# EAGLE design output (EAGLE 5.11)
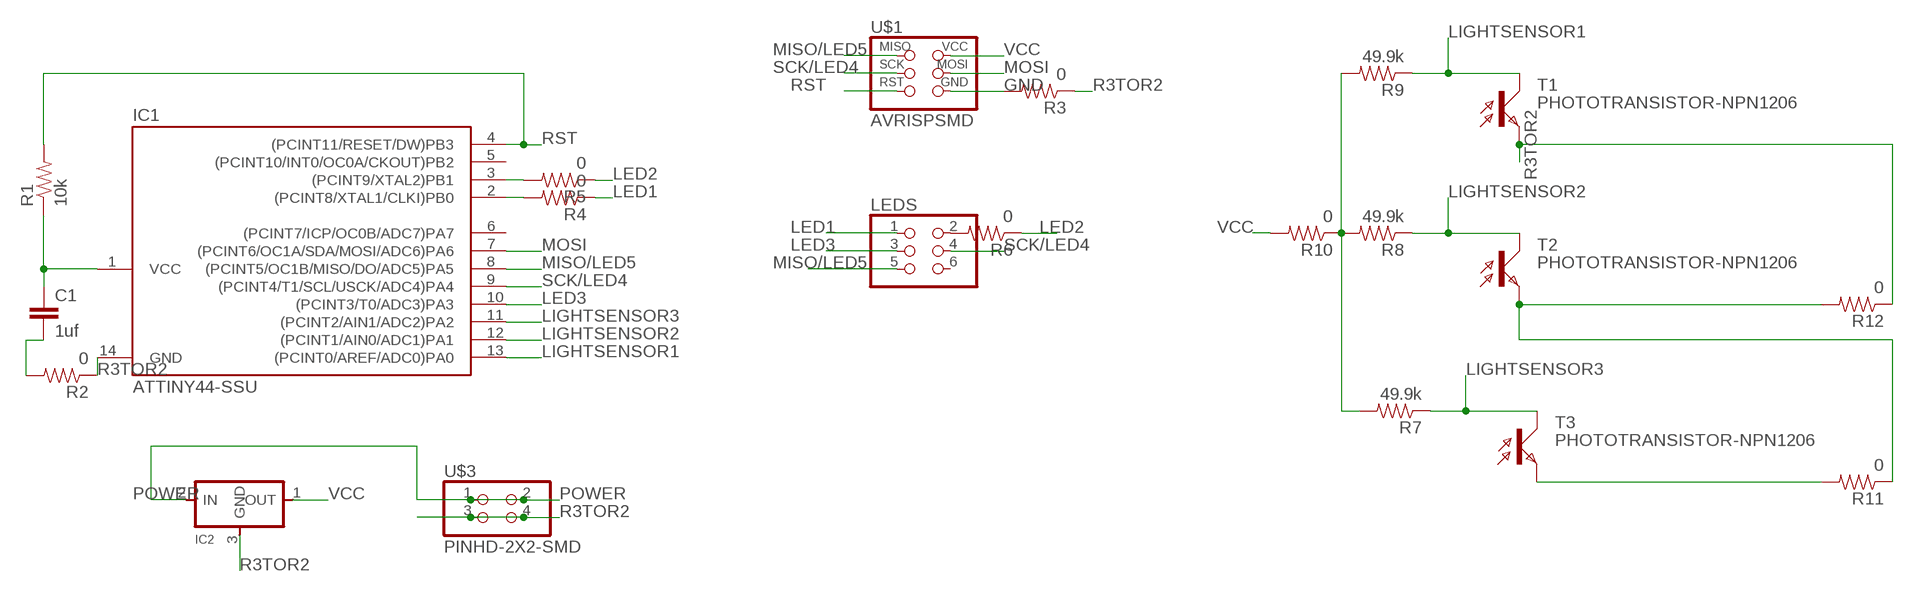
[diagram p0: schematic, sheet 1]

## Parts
C1  1uf  CAP1206  [1206]
IC1  ATTINY44-SSU  [SOIC14]
IC2  REGULATORSOT23  [SOT23]
LEDS  PINHD-2X3-SMD  [2X03SMD]
R1  10k  RESISTOR1206  [1206]
R2  0  RESISTOR1206  [1206]
R3  0  RESISTOR1206  [1206]
R4  0  RESISTOR1206  [1206]
R5  0  RESISTOR1206  [1206]
R6  0  RESISTOR1206  [1206]
R7  49.9k  RESISTOR1206  [1206]
R8  49.9k  RESISTOR1206  [1206]
R9  49.9k  RESISTOR1206  [1206]
R10  0  RESISTOR1206  [1206]
R11  0  RESISTOR1206  [1206]
R12  0  RESISTOR1206  [1206]
T1  PHOTOTRANSISTOR-NPN1206  [OP1206]
T2  PHOTOTRANSISTOR-NPN1206  [OP1206]
T3  PHOTOTRANSISTOR-NPN1206  [OP1206]
U$1  AVRISPSMD  [2X03SMD]
U$3  PINHD-2X2-SMD  [2X02SMD]

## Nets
GND: R3.2 U$1.6(GND)
LED1: LEDS.1 R4.1
LED2: R5.1 R6.1
LED3: IC1.10((PCINT3/T0/ADC3)PA3) LEDS.3
LIGHTSENSOR1: IC1.13((PCINT0/AREF/ADC0)PA0) R9.1 T1.COLLECTOR(C)
LIGHTSENSOR2: IC1.12((PCINT1/AIN0/ADC1)PA1) R8.1 T2.COLLECTOR(C)
LIGHTSENSOR3: IC1.11((PCINT2/AIN1/ADC2)PA2) R7.1 T3.COLLECTOR(C)
MISO/LED5: IC1.8((PCINT5/OC1B/MISO/DO/ADC5)PA5) LEDS.5 U$1.1(MISO)
MOSI: IC1.7((PCINT6/OC1A/SDA/MOSI/ADC6)PA6) U$1.4(MOSI)
N$1: IC1.3((PCINT9/XTAL2)PB1) R5.2
N$2: C1.2 R2.2
N$3: IC1.2((PCINT8/XTAL1/CLKI)PB0) R4.2
N$4: LEDS.2 R6.2
N$5: R7.2 R8.2 R9.2 R10.1
N$6: R11.2 T3.EMITTER(E)
N$7: R11.1 R12.2 T2.EMITTER(E)
POWER: IC2.2(IN) U$3.1 U$3.2
R3TOR2: IC1.14(GND) IC2.3(GND) R2.1 R3.1 R12.1 T1.EMITTER(E) U$3.3 U$3.4
RST: IC1.4((PCINT11/RESET/DW)PB3) R1.2 U$1.5(RST)
SCK/LED4: IC1.9((PCINT4/T1/SCL/USCK/ADC4)PA4) LEDS.4 U$1.3(SCK)
VCC: C1.1 IC1.1(VCC) IC2.1(OUT) R1.1 R10.2 U$1.2(VCC)
Unconnected: IC1.5((PCINT10/INT0/OC0A/CKOUT)PB2) IC1.6((PCINT7/ICP/OC0B/ADC7)PA7) LEDS.6

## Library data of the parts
C1 = SparkFun:CAP: Capacitor
IC1 = fab:ATTINY44
IC2 = ng:REGULATOR
LEDS = fab:PINHD-2X3-SMD: PIN HEADER
R1-R12 = SparkFun:RESISTOR: Resistor
T1-T3 = fab:PHOTOTRANSISTOR-NPN
U$1 = fab:AVRISP
U$3 = fab:PINHD-2X2-SMD

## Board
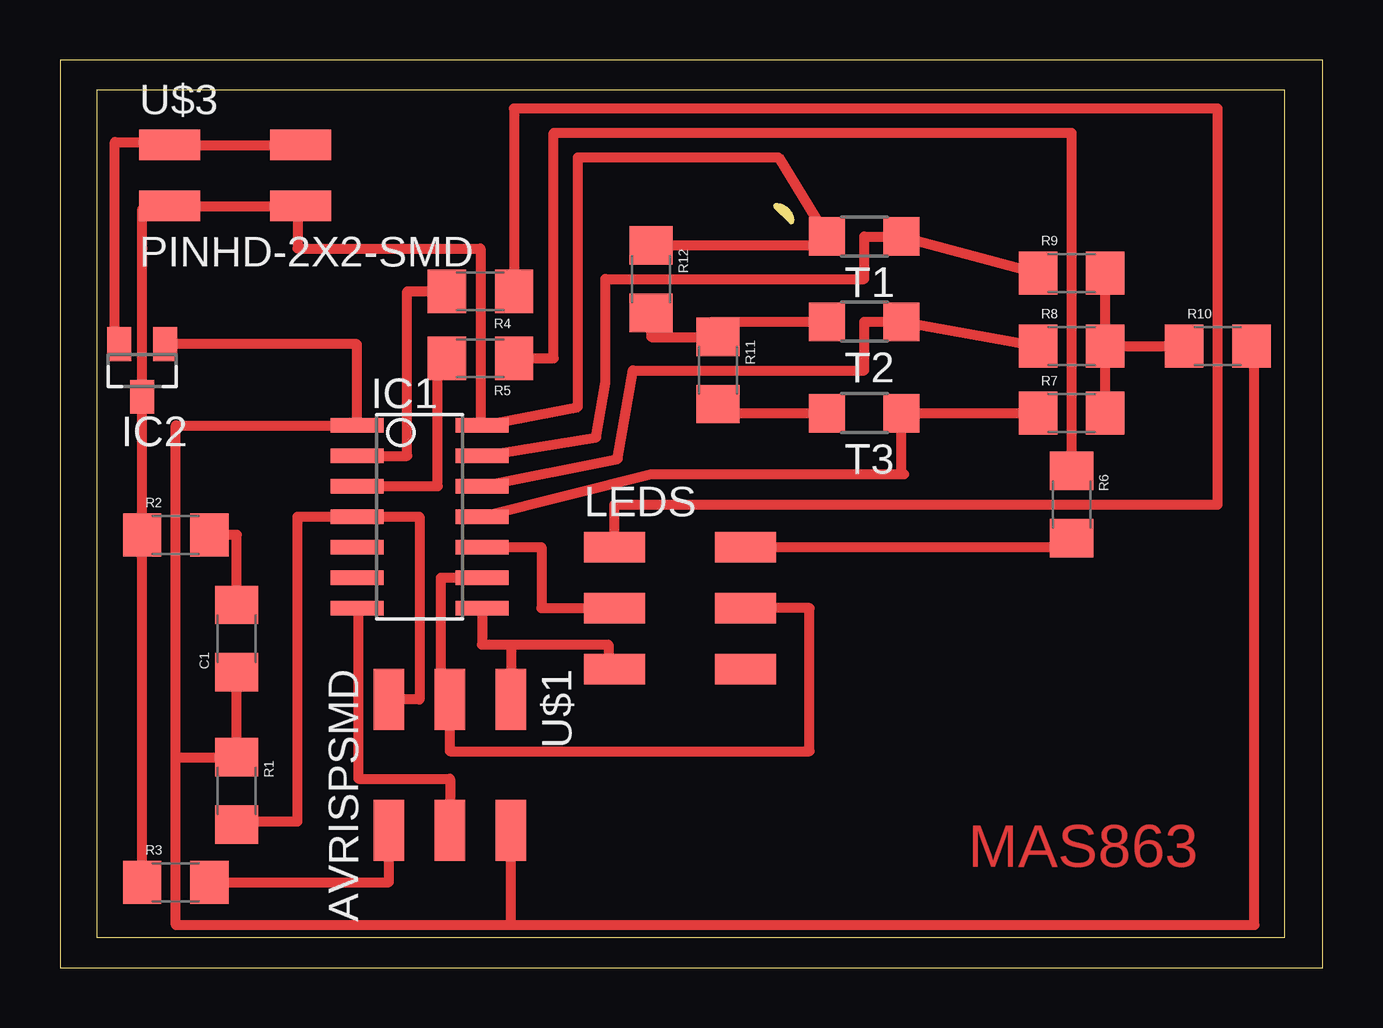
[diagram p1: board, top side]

Size 52.63 x 37.84 mm. Coordinates in mm from the lower left corner, seen from the top.
Outline: 0,0 52.63,0 52.63,37.84 0,37.84 0,0
Copper layers 1: Top 0.035mm
Design rules "ERP-1sided-10mil-16mill": minimum track width 10mil, minimum drill 24mil, track to track 16mil, track to pad 16mil, pad to pad 16mil, via to via 16mil, smd to smd 0mil, copper to edge 16mil, drill to drill 36mil, minimum pad ring 10mil, minimum via ring 8mil, stop-mask expansion 4mil, vias tented up to drill 0mil, thermal gap 10mil
Milling: area 29.8,31.1 to 30.5,31.8; area 1.5,1.3 to 51.1,36.6

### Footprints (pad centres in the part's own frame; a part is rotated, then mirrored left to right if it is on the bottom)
1206 = smd 1.6 x 1.8: 1 -1.4,0; 2 1.4,0
SOIC14 = smd 0.61 x 2.21: 1 -3.81,-2.603; 2 -2.54,-2.603; 3 -1.27,-2.603; 4 0,-2.603; 5 1.27,-2.603; 6 2.54,-2.603; 7 3.81,-2.603; 8 3.81,2.603; 9 2.54,2.603; 10 1.27,2.603; 11 0,2.603; 12 -1.27,2.603; 13 -2.54,2.603; 14 -3.81,2.603
SOT23 = smd 1 x 1.4: 1 -0.95,-1.1; 2 0.95,-1.1; 3 0,1.1
2X03SMD = smd 2.54 x 1.27: 1 -2.54,2.54; 2 2.92,2.54; 3 -2.54,0; 4 2.92,0; 5 -2.54,-2.54; 6 2.92,-2.54
OP1206 = smd 1.5 x 1.6: COLLECTOR -1.55,0; EMITTER 1.55,0
2X02SMD = smd 2.54 x 1.27: 1 -2.54,1.27; 2 2.92,1.27; 3 -2.54,-1.27; 4 2.92,-1.27

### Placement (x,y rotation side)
C1  7.37,13.72 90 top
IC1  14.99,18.8 270 top
IC2  3.43,24.89 180 top
LEDS  25.65,14.99 0 top
R1  7.37,7.37 270 top
R2  4.83,18.03 0 top
R3  4.83,3.56 0 top
R4  17.53,28.19 180 top
R5  17.53,25.4 180 top
R6  42.16,19.3 270 top
R7  42.16,23.11 0 top
R8  42.16,25.91 0 top
R9  42.16,28.96 0 top
R10  48.26,25.91 0 top
R11  27.43,24.89 270 top
R12  24.64,28.7 270 top
T1  33.53,30.48 180 top
T2  33.53,26.92 180 top
T3  33.53,23.11 180 top
U$1  16.26,8.64 270 top
U$3  7.11,33.02 0 top

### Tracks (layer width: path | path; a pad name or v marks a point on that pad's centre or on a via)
GND
  Top 0.406: U$1.6 13.72,3.56 R3.2
LED1
  Top 0.406: LEDS.1 23.11,19.3 48.26,19.3 48.26,35.81 18.93,35.81 R4.1
LED2
  Top 0.406: R5.1 20.57,25.4 20.57,34.8 42.16,34.8 R6.1
LED3
  Top 0.406: IC1.10 20.07,17.53 20.07,14.99 LEDS.3
LIGHTSENSOR1
  Top 0.406: R9.1 T1.COLLECTOR 33.53,30.48 33.53,28.7 22.73,28.7 22.73,24.38 22.35,22.1 IC1.13
LIGHTSENSOR2
  Top 0.406: R8.1 T2.COLLECTOR 33.53,26.92 33.53,24.89 23.88,24.89 23.24,21.21 IC1.12
LIGHTSENSOR3
  Top 0.406: T3.COLLECTOR R7.1 | T3.COLLECTOR 35.05,22.86 | IC1.11 24.64,20.57 35.08,20.57 | 35.08,20.57 35.18,20.57 | 35.08,20.57 T3.COLLECTOR
MISO/LED5
  Top 0.406: 18.8,13.46 U$1.1 | 18.8,13.46 17.59,13.46 IC1.8 | LEDS.5 22.86,12.45 22.86,13.46 18.8,13.46
MOSI
  Top 0.406: IC1.7 12.45,14.99 12.45,7.87 16.26,7.87 U$1.4
N$1
  Top 0.406: IC1.3 15.75,20.07 15.75,25.15 16.13,25.15 R5.2
N$2
  Top 0.406: R2.2 7.37,18.03 C1.2
N$3
  Top 0.406: IC1.2 14.48,21.34 14.48,28.19 R4.2
N$4
  Top 0.406: LEDS.2 42.16,17.53 R6.2
N$5
  Top 0.406: R8.2 R10.1 | R8.2 R9.2 | R7.2 R8.2
N$6
  Top 0.406: T3.EMITTER 27.43,23.11 R11.2
N$7
  Top 0.406: T2.EMITTER 27.18,26.92 27.18,26.67 27.43,26.67 R11.1 24.64,26.29 R12.2
POWER
  Top 0.406: IC2.2 2.29,25.99 2.29,34.42 4.57,34.42 U$3.1 U$3.2
R3TOR2
  Top 0.406: IC2.3 3.43,29.97 3.43,31.62 4.57,31.62 U$3.3 U$3.4 9.91,31.75 9.91,29.97 17.53,29.97 17.53,22.61 IC1.14 21.59,23.37 21.59,33.78 29.95,33.78 T1.EMITTER 31.98,30.1 R12.1 | R3.1 R2.1 IC2.3 | IC2.3
RST
  Top 0.406: R1.2 7.37,6.1 9.91,6.1 9.91,18.8 IC1.4 14.99,18.8 14.99,11.18 U$1.5
SCK/LED4
  Top 0.406: U$1.3 16,11.18 | LEDS.4 31.24,14.99 31.24,9.02 16.26,9.02 U$1.3 | IC1.9 15.88,16.26 15.88,11.81 16.26,11.81 U$1.3
VCC
  Top 0.406: C1.1 R1.1 4.83,8.77 | 4.83,8.77 4.83,22.61 IC1.1 12.38,25.99 IC2.1 | 18.8,1.78 U$1.2 | 18.8,1.78 4.83,1.78 4.83,8.77 | 18.8,1.78 49.78,1.78 49.78,25.15 49.66,25.15 R10.2

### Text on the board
Top: MAS863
